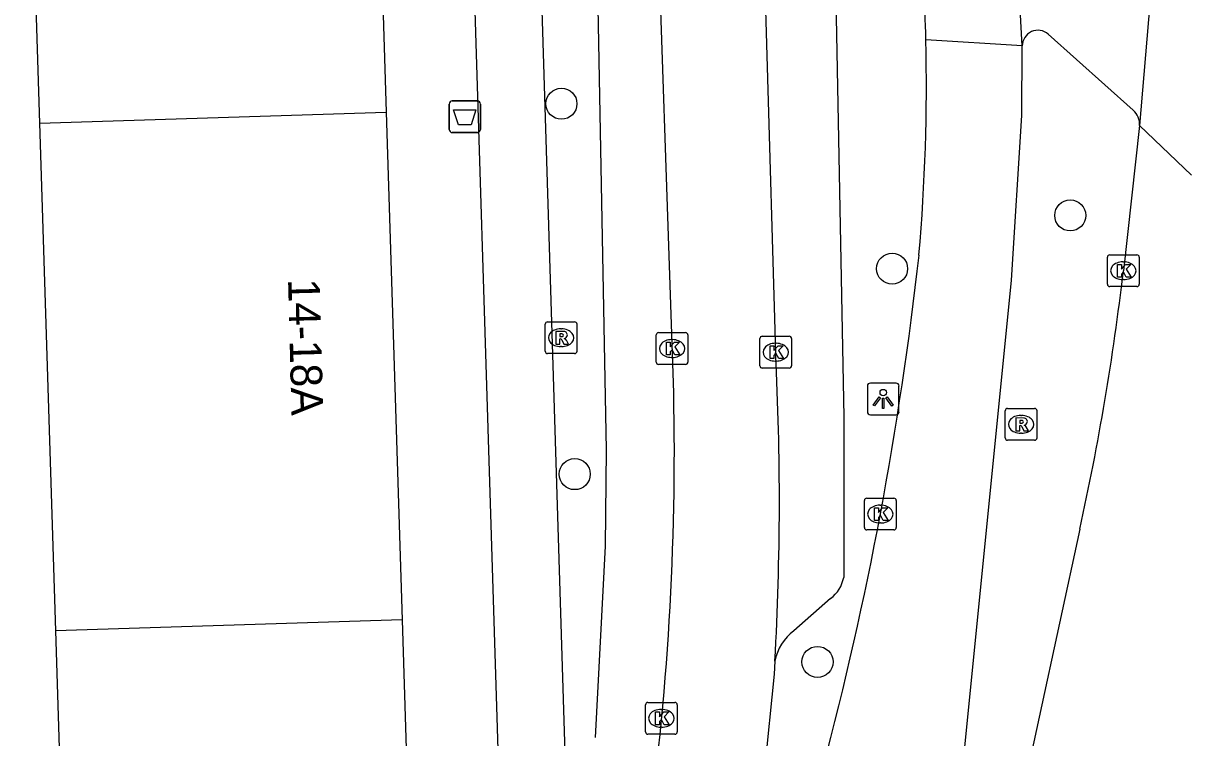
# Model space of a CAD drawing. Extents: x 161402 to 161933, y 381650 to 382313.
# Drawn here: x 161896.28 to 161933.1, y 382106.69 to 382129.18 of the extents above; entities that cross this region are included whole.
import ezdxf

# ---------------------------------------------------------------- set-up
doc = ezdxf.new("R2010")
doc.units = 0
for name, color, linetype in [('IMGEO_Afvalbak', 7, 'Continuous'), ('IMGEO_Boom', 7, 'Continuous'), ('IMGEO_Fietspad_open', 7, 'Continuous'), ('IMGEO_Kolk', 7, 'Continuous'), ('IMGEO_Lichtpunt', 7, 'Continuous'), ('IMGEO_OVBaan_gesloten', 7, 'Continuous'), ('IMGEO_Pand', 7, 'Continuous'), ('IMGEO_Pand_nummerreeks', 7, 'Continuous'), ('IMGEO_Parkeervlak_open', 7, 'Continuous'), ('IMGEO_Rijbaan_lokaal_gesloten', 7, 'Continuous'), ('IMGEO_Rijbaan_lokaal_open', 7, 'Continuous'), ('IMGEO_Rioolput', 7, 'Continuous'), ('IMGEO_Voetpad_open', 7, 'Continuous')]:
    doc.layers.add(name, color=color, linetype=linetype)

msp = doc.modelspace()

# ---------------------------------------------------------------- linework, layer by layer
at = {"layer": 'IMGEO_Afvalbak'}
for p, q in [((161909.801, 382126.741), (161910.591, 382126.741)), ((161910.591, 382126.741), (161909.801, 382126.741)), ((161909.701, 382125.841), (161909.701, 382126.641)), ((161909.701, 382126.641), (161909.701, 382125.841)), ((161910.691, 382126.641), (161910.691, 382125.841)), ((161910.691, 382125.841), (161910.691, 382126.641)), ((161910.591, 382125.741), (161909.801, 382125.741)), ((161909.801, 382125.741), (161910.591, 382125.741))]:
    msp.add_line(p, q, dxfattribs=at)
msp.add_lwpolyline([(161909.844, 382126.455), (161910.548, 382126.455), (161910.399, 382125.985), (161909.993, 382125.985), (161909.844, 382126.455)], dxfattribs=at)
for centre, start, end in [((161909.801, 382126.641), 90, 180), ((161909.801, 382126.641), 90, 180), ((161910.591, 382126.641), 0, 90), ((161910.591, 382126.641), 360, 90), ((161909.801, 382125.841), 180, 270), ((161909.801, 382125.841), 180, 270), ((161910.591, 382125.841), 270, 0), ((161910.591, 382125.841), 270, 0)]:
    msp.add_arc(centre, 0.1, start, end, dxfattribs=at)
at = {"layer": 'IMGEO_Boom'}
for centre in [(161913.241, 382126.651), (161929.275, 382123.133), (161923.662, 382121.455), (161913.66, 382114.984), (161921.31, 382109.069)]:
    msp.add_circle(centre, 0.489, dxfattribs=at)
at = {"layer": 'IMGEO_Fietspad_open'}
for points in [[(161912.16, 382144.813), (161912.252, 382141.473), (161913.518, 382100.778), (161913.546, 382089.832), (161913.149, 382075.567)], [(161911.019, 382075.595), (161911.485, 382092.573), (161911.516, 382094.566), (161911.423, 382100.579), (161910.052, 382144.744)]]:
    msp.add_lwpolyline(points, dxfattribs=at)
at = {"layer": 'IMGEO_Kolk'}
for p, q in [((161930.447, 382120.964), (161930.447, 382121.816)), ((161930.522, 382121.89), (161931.374, 382121.89)), ((161930.935, 382121.67), (161930.96, 382121.67)), ((161931.448, 382121.816), (161931.448, 382120.964)), ((161931.374, 382120.89), (161930.522, 382120.89)), ((161930.958, 382121.11), (161930.933, 382121.11)), ((161916.301, 382119.44), (161917.153, 382119.44)), ((161916.226, 382118.514), (161916.226, 382119.366)), ((161916.714, 382119.22), (161916.739, 382119.22)), ((161917.227, 382119.366), (161917.227, 382118.514)), ((161919.494, 382118.399), (161919.494, 382119.251)), ((161919.569, 382119.325), (161920.421, 382119.325)), ((161919.982, 382119.105), (161920.007, 382119.105)), ((161920.495, 382119.251), (161920.495, 382118.399)), ((161916.737, 382118.66), (161916.712, 382118.66)), ((161917.153, 382118.44), (161916.301, 382118.44)), ((161920.421, 382118.325), (161919.569, 382118.325)), ((161920.005, 382118.545), (161919.98, 382118.545)), ((161922.864, 382114.225), (161923.716, 382114.225)), ((161922.789, 382113.299), (161922.789, 382114.151)), ((161923.277, 382114.005), (161923.302, 382114.005)), ((161923.79, 382114.151), (161923.79, 382113.299)), ((161923.716, 382113.225), (161922.864, 382113.225)), ((161923.3, 382113.445), (161923.275, 382113.445)), ((161915.889, 382106.867), (161915.889, 382107.719)), ((161915.964, 382107.793), (161916.816, 382107.793)), ((161916.89, 382107.719), (161916.89, 382106.867)), ((161916.377, 382107.573), (161916.402, 382107.573)), ((161916.4, 382107.013), (161916.375, 382107.013)), ((161916.816, 382106.793), (161915.964, 382106.793))]:
    msp.add_line(p, q, dxfattribs=at)
for points in [[(161930.447, 382120.964), (161930.447, 382121.816)], [(161930.522, 382121.89), (161931.374, 382121.89)], [(161930.768, 382121.59), (161930.891, 382121.59), (161930.891, 382121.439), (161931.021, 382121.59), (161931.185, 382121.59), (161931.039, 382121.439), (161931.192, 382121.19), (161931.04, 382121.19), (161930.955, 382121.354), (161930.891, 382121.287), (161930.891, 382121.19), (161930.768, 382121.19), (161930.768, 382121.59)], [(161931.448, 382121.816), (161931.448, 382120.964)], [(161931.374, 382120.89), (161930.522, 382120.89)], [(161916.301, 382119.44), (161917.153, 382119.44)], [(161916.226, 382118.514), (161916.226, 382119.366)], [(161916.547, 382119.14), (161916.67, 382119.14), (161916.67, 382118.989), (161916.8, 382119.14), (161916.964, 382119.14), (161916.818, 382118.989), (161916.971, 382118.74), (161916.819, 382118.74), (161916.734, 382118.904), (161916.67, 382118.837), (161916.67, 382118.74), (161916.547, 382118.74), (161916.547, 382119.14)], [(161917.227, 382119.366), (161917.227, 382118.514)], [(161919.494, 382118.399), (161919.494, 382119.251)], [(161919.569, 382119.325), (161920.421, 382119.325)], [(161919.815, 382119.025), (161919.938, 382119.025), (161919.938, 382118.874), (161920.068, 382119.025), (161920.232, 382119.025), (161920.086, 382118.874), (161920.239, 382118.625), (161920.087, 382118.625), (161920.002, 382118.789), (161919.938, 382118.722), (161919.938, 382118.625), (161919.815, 382118.625), (161919.815, 382119.025)], [(161920.495, 382119.251), (161920.495, 382118.399)], [(161917.153, 382118.44), (161916.301, 382118.44)], [(161920.421, 382118.325), (161919.569, 382118.325)], [(161922.864, 382114.225), (161923.716, 382114.225)], [(161922.789, 382113.299), (161922.789, 382114.151)], [(161923.11, 382113.925), (161923.233, 382113.925), (161923.233, 382113.774), (161923.363, 382113.925), (161923.527, 382113.925), (161923.381, 382113.774), (161923.534, 382113.525), (161923.382, 382113.525), (161923.297, 382113.689), (161923.233, 382113.622), (161923.233, 382113.525), (161923.11, 382113.525), (161923.11, 382113.925)], [(161923.79, 382114.151), (161923.79, 382113.299)], [(161923.716, 382113.225), (161922.864, 382113.225)], [(161915.889, 382106.867), (161915.889, 382107.719)], [(161915.964, 382107.793), (161916.816, 382107.793)], [(161916.89, 382107.719), (161916.89, 382106.867)], [(161916.21, 382107.493), (161916.333, 382107.493), (161916.333, 382107.342), (161916.463, 382107.493), (161916.627, 382107.493), (161916.481, 382107.342), (161916.634, 382107.093), (161916.482, 382107.093), (161916.397, 382107.257), (161916.333, 382107.19), (161916.333, 382107.093), (161916.21, 382107.093), (161916.21, 382107.493)], [(161916.816, 382106.793), (161915.964, 382106.793)]]:
    msp.add_lwpolyline(points, dxfattribs=at)
for centre, start, end in [((161930.524, 382121.814), 91.552, 178.448), ((161930.524, 382121.814), 91.552, 178.448), ((161931.372, 382121.814), 1.552, 88.448), ((161931.372, 382121.814), 1.552, 88.448), ((161930.524, 382120.966), 181.552, 268.448), ((161930.524, 382120.966), 181.552, 268.448), ((161931.372, 382120.966), 271.552, 358.448), ((161931.372, 382120.966), 271.552, 358.448), ((161916.303, 382119.364), 91.552, 178.448), ((161916.303, 382119.364), 91.552, 178.448), ((161917.151, 382119.364), 1.552, 88.448), ((161917.151, 382119.364), 1.552, 88.448), ((161919.571, 382119.249), 91.552, 178.448), ((161919.571, 382119.249), 91.552, 178.448), ((161920.419, 382119.249), 1.552, 88.448), ((161920.419, 382119.249), 1.552, 88.448), ((161916.303, 382118.516), 181.552, 268.448), ((161916.303, 382118.516), 181.552, 268.448), ((161917.151, 382118.516), 271.552, 358.448), ((161917.151, 382118.516), 271.552, 358.448), ((161919.571, 382118.401), 181.552, 268.448), ((161919.571, 382118.401), 181.552, 268.448), ((161920.419, 382118.401), 271.552, 358.448), ((161920.419, 382118.401), 271.552, 358.448), ((161922.866, 382114.149), 91.552, 178.448), ((161922.866, 382114.149), 91.552, 178.448), ((161923.714, 382114.149), 1.552, 88.448), ((161923.714, 382114.149), 1.552, 88.448), ((161922.866, 382113.301), 181.552, 268.448), ((161922.866, 382113.301), 181.552, 268.448), ((161923.714, 382113.301), 271.552, 358.448), ((161923.714, 382113.301), 271.552, 358.448), ((161915.966, 382107.717), 91.552, 178.448), ((161915.966, 382107.717), 91.552, 178.448), ((161916.814, 382107.717), 1.552, 88.448), ((161916.814, 382107.717), 1.552, 88.448), ((161915.966, 382106.869), 181.552, 268.448), ((161915.966, 382106.869), 181.552, 268.448), ((161916.814, 382106.869), 271.552, 358.448), ((161916.814, 382106.869), 271.552, 358.448)]:
    msp.add_arc(centre, 0.0765, start, end, dxfattribs=at)
for centre, major_axis, ratio, start_param, end_param in [((161930.934, 382121.39), (-0.387, 0.002), 0.722429, 4.712389, 7.853982), ((161930.959, 382121.39), (-0.39, 0.002), 0.717154, 1.570796, 4.712389), ((161916.713, 382118.94), (-0.387, 0.002), 0.722429, 4.712389, 7.853982), ((161916.738, 382118.94), (-0.39, 0.002), 0.717154, 1.570796, 4.712389), ((161919.981, 382118.825), (-0.387, 0.002), 0.722429, 4.712389, 7.853982), ((161920.006, 382118.825), (-0.39, 0.002), 0.717154, 1.570796, 4.712389), ((161923.276, 382113.725), (-0.387, 0.002), 0.722429, 4.712389, 7.853982), ((161923.301, 382113.725), (-0.39, 0.002), 0.717154, 1.570796, 4.712389), ((161916.376, 382107.293), (-0.387, 0.002), 0.722429, 4.712389, 7.853982), ((161916.401, 382107.293), (-0.39, 0.002), 0.717154, 1.570796, 4.712389)]:
    msp.add_ellipse(centre, major_axis=major_axis, ratio=ratio, start_param=start_param, end_param=end_param, dxfattribs=at)
at = {"layer": 'IMGEO_Lichtpunt'}
for p, q in [((161922.882, 382117.756), (161922.882, 382116.949)), ((161922.882, 382117.756), (161922.882, 382116.949)), ((161923.784, 382117.851), (161922.976, 382117.851)), ((161923.784, 382117.851), (161922.976, 382117.851)), ((161923.878, 382116.949), (161923.878, 382117.756)), ((161923.878, 382116.949), (161923.878, 382117.756)), ((161922.976, 382116.855), (161923.784, 382116.855)), ((161922.976, 382116.855), (161923.784, 382116.855))]:
    msp.add_line(p, q, dxfattribs=at)
for points in [[(161923.256, 382117.42), (161923.295, 382117.392), (161923.107, 382117.13), (161923.069, 382117.157), (161923.256, 382117.42)], [(161923.358, 382117.372), (161923.405, 382117.372), (161923.405, 382117.05), (161923.358, 382117.05), (161923.358, 382117.372)], [(161923.468, 382117.392), (161923.506, 382117.419), (161923.693, 382117.157), (161923.654, 382117.129), (161923.468, 382117.392)]]:
    msp.add_lwpolyline(points, dxfattribs=at)
msp.add_circle((161923.381, 382117.554), 0.0994, dxfattribs=at)
for centre, start, end in [((161922.976, 382117.756), 90, 180), ((161922.976, 382117.756), 90, 180), ((161923.784, 382117.756), 0, 90), ((161923.784, 382117.756), 0, 90), ((161922.976, 382116.949), 180, 270), ((161922.976, 382116.949), 180, 270), ((161923.784, 382116.949), 270, 0), ((161923.784, 382116.949), 270, 360)]:
    msp.add_arc(centre, 0.0946, start, end, dxfattribs=at)
at = {"layer": 'IMGEO_OVBaan_gesloten'}
for points in [[(161931.782, 382129.797), (161931.462, 382125.963)], [(161931.462, 382125.963), (161930.949, 382121.39)], [(161931.462, 382125.963), (161933.101, 382124.399)], [(161929.574, 382113.249), (161927.659, 382104.365)]]:
    msp.add_lwpolyline(points, dxfattribs=at)
msp.add_arc((161851.018, 382130.704), 80.472, 347.47281, 353.35384, dxfattribs=at)
at = {"layer": 'IMGEO_Pand'}
for points in [[(161907.227, 382142.376), (161907.722, 382126.383)], [(161896.284, 382142.031), (161896.788, 382126.039)], [(161896.788, 382126.039), (161907.722, 382126.383)], [(161907.722, 382126.383), (161908.217, 382110.391)], [(161896.788, 382126.039), (161897.292, 382110.047)], [(161908.217, 382110.391), (161897.292, 382110.047)], [(161908.217, 382110.391), (161908.71, 382094.477), (161908.715, 382094.318), (161908.487, 382094.311)], [(161897.292, 382110.047), (161897.788, 382094.302), (161897.528, 382094.294), (161897.538, 382093.965)]]:
    msp.add_lwpolyline(points, dxfattribs=at)
at = {"layer": 'IMGEO_Parkeervlak_open'}
for points in [[(161921.789, 382134.855), (161922.143, 382116.78), (161922.135, 382111.73)], [(161914.31, 382106.685), (161914.634, 382112.711), (161914.66, 382115.753), (161914.358, 382131.92)], [(161921.722, 382111.072), (161920.563, 382110.053)]]:
    msp.add_lwpolyline(points, dxfattribs=at)
for centre, radius, start, end in [((161921.109, 382111.915), 1.043, 306.0149, 349.7554), ((161921.527, 382108.79), 1.588, 127.362, 169.1313)]:
    msp.add_arc(centre, radius, start, end, dxfattribs=at)
at = {"layer": 'IMGEO_Rijbaan_lokaal_gesloten'}
for points in [[(161927.762, 382128.469), (161927.527, 382132.744)], [(161927.762, 382128.469), (161924.726, 382128.664)], [(161925.781, 382104.703), (161927.423, 382121.095), (161927.747, 382126.278), (161927.762, 382128.469)]]:
    msp.add_lwpolyline(points, dxfattribs=at)
for centre, radius, start, end in [((161862.475, 382127.256), 62.267, 1.29538, 4.51131), ((161862.23, 382127.272), 62.511, 355.05674, 1.27637), ((161814.253, 382134.176), 110.939, 345.12266, 353.63931)]:
    msp.add_arc(centre, radius, start, end, dxfattribs=at)
at = {"layer": 'IMGEO_Rijbaan_lokaal_open'}
for points in [[(161919.422, 382138.255), (161919.989, 382118.8)], [(161916.779, 382117.545), (161916.189, 382135.151)], [(161919.967, 382109.09), (161919.943, 382108.679), (161919.334, 382102.678), (161918.737, 382098.388)]]:
    msp.add_lwpolyline(points, dxfattribs=at)
for centre, radius, start, end in [((161830.077, 382114.149), 90.032, 356.77898, 2.96138), ((161829.113, 382115.663), 87.686, 351.84266, 1.22982)]:
    msp.add_arc(centre, radius, start, end, dxfattribs=at)
at = {"layer": 'IMGEO_Rioolput'}
for p, q in [((161912.805, 382119.78), (161913.657, 382119.78)), ((161912.73, 382118.854), (161912.73, 382119.706)), ((161913.218, 382119.56), (161913.243, 382119.56)), ((161913.731, 382119.706), (161913.731, 382118.854)), ((161913.657, 382118.78), (161912.805, 382118.78)), ((161913.241, 382119), (161913.216, 382119)), ((161927.226, 382116.126), (161927.226, 382116.978)), ((161927.301, 382117.052), (161928.153, 382117.052)), ((161927.714, 382116.832), (161927.739, 382116.832)), ((161928.227, 382116.978), (161928.227, 382116.126)), ((161927.737, 382116.272), (161927.712, 382116.272)), ((161928.153, 382116.052), (161927.301, 382116.052))]:
    msp.add_line(p, q, dxfattribs=at)
for points in [[(161912.805, 382119.78), (161913.657, 382119.78)], [(161912.73, 382118.854), (161912.73, 382119.706)], [(161913.319, 382119.478), (161913.067, 382119.48), (161913.067, 382119.08)], [(161913.245, 382119.399), (161913.191, 382119.399), (161913.191, 382119.318)], [(161913.731, 382119.706), (161913.731, 382118.854)], [(161913.067, 382119.08), (161913.191, 382119.08), (161913.191, 382119.242), (161913.202, 382119.242)], [(161913.191, 382119.318), (161913.243, 382119.318)], [(161913.249, 382119.213), (161913.32, 382119.08), (161913.46, 382119.08), (161913.395, 382119.206)], [(161913.657, 382118.78), (161912.805, 382118.78)], [(161927.226, 382116.126), (161927.226, 382116.978)], [(161927.301, 382117.052), (161928.153, 382117.052)], [(161928.227, 382116.978), (161928.227, 382116.126)], [(161927.815, 382116.75), (161927.563, 382116.752), (161927.563, 382116.352)], [(161927.563, 382116.352), (161927.687, 382116.352), (161927.687, 382116.514), (161927.698, 382116.514)], [(161927.741, 382116.671), (161927.687, 382116.671), (161927.687, 382116.59)], [(161927.687, 382116.59), (161927.739, 382116.59)], [(161927.745, 382116.485), (161927.816, 382116.352), (161927.956, 382116.352), (161927.891, 382116.478)], [(161928.153, 382116.052), (161927.301, 382116.052)]]:
    msp.add_lwpolyline(points, dxfattribs=at)
for centre, radius, start, end in [((161912.807, 382119.704), 0.0765, 91.552, 178.448), ((161912.807, 382119.704), 0.0765, 91.552, 178.448), ((161913.655, 382119.704), 0.0765, 1.552, 88.448), ((161913.655, 382119.704), 0.0765, 1.552, 88.448), ((161913.251, 382119.303), 0.0964, 77.0061, 93.1865), ((161913.265, 382119.36), 0.0378, 276.6634, 79.6772), ((161913.318, 382119.368), 0.109, 350.3612, 89.416), ((161913.201, 382119.189), 0.0533, 26.0293, 88.6989), ((161913.227, 382119.507), 0.19, 274.7715, 282.9687), ((161913.316, 382119.368), 0.112, 277.5842, 350.9817), ((161913.3, 382119.153), 0.108, 29.5134, 73.7905), ((161912.807, 382118.856), 0.0765, 181.552, 268.448), ((161912.807, 382118.856), 0.0765, 181.552, 268.448), ((161913.655, 382118.856), 0.0765, 271.552, 358.448), ((161913.655, 382118.856), 0.0765, 271.552, 358.448), ((161927.303, 382116.976), 0.0765, 91.552, 178.448), ((161927.303, 382116.976), 0.0765, 91.552, 178.448), ((161928.151, 382116.976), 0.0765, 1.552, 88.448), ((161928.151, 382116.976), 0.0765, 1.552, 88.448), ((161927.697, 382116.461), 0.0533, 26.0293, 88.6989), ((161927.723, 382116.779), 0.19, 274.7715, 282.9687), ((161927.747, 382116.575), 0.0964, 77.0061, 93.1865), ((161927.761, 382116.632), 0.0378, 276.6634, 79.6772), ((161927.814, 382116.64), 0.109, 350.3612, 89.416), ((161927.812, 382116.64), 0.112, 277.5842, 350.9817), ((161927.796, 382116.425), 0.108, 29.5134, 73.7905), ((161927.303, 382116.128), 0.0765, 181.552, 268.448), ((161927.303, 382116.128), 0.0765, 181.552, 268.448), ((161928.151, 382116.128), 0.0765, 271.552, 358.448), ((161928.151, 382116.128), 0.0765, 271.552, 358.448)]:
    msp.add_arc(centre, radius, start, end, dxfattribs=at)
for centre, major_axis, ratio, start_param, end_param in [((161913.217, 382119.28), (-0.387, 0.002), 0.722429, 4.712389, 7.853982), ((161913.242, 382119.28), (-0.39, 0.002), 0.717154, 1.570796, 4.712389), ((161927.713, 382116.552), (-0.387, 0.002), 0.722429, 4.712389, 7.853982), ((161927.738, 382116.552), (-0.39, 0.002), 0.717154, 1.570796, 4.712389)]:
    msp.add_ellipse(centre, major_axis=major_axis, ratio=ratio, start_param=start_param, end_param=end_param, dxfattribs=at)
at = {"layer": 'IMGEO_Voetpad_open'}
msp.add_lwpolyline([(161931.257, 382126.445), (161928.583, 382128.841)], dxfattribs=at)
for centre, radius, start, end in [((161928.257, 382128.469), 0.495, 48.7291, 180.022), ((161930.865, 382125.994), 0.597, 357.0391, 49.042)]:
    msp.add_arc(centre, radius, start, end, dxfattribs=at)

# ---------------------------------------------------------------- texts
at = {"layer": 'IMGEO_Pand_nummerreeks'}
msp.add_text('14-18A', height=1, rotation=271.4755, dxfattribs=at).set_placement((161904.624, 382121.129))

doc.saveas('drawing.dxf')
